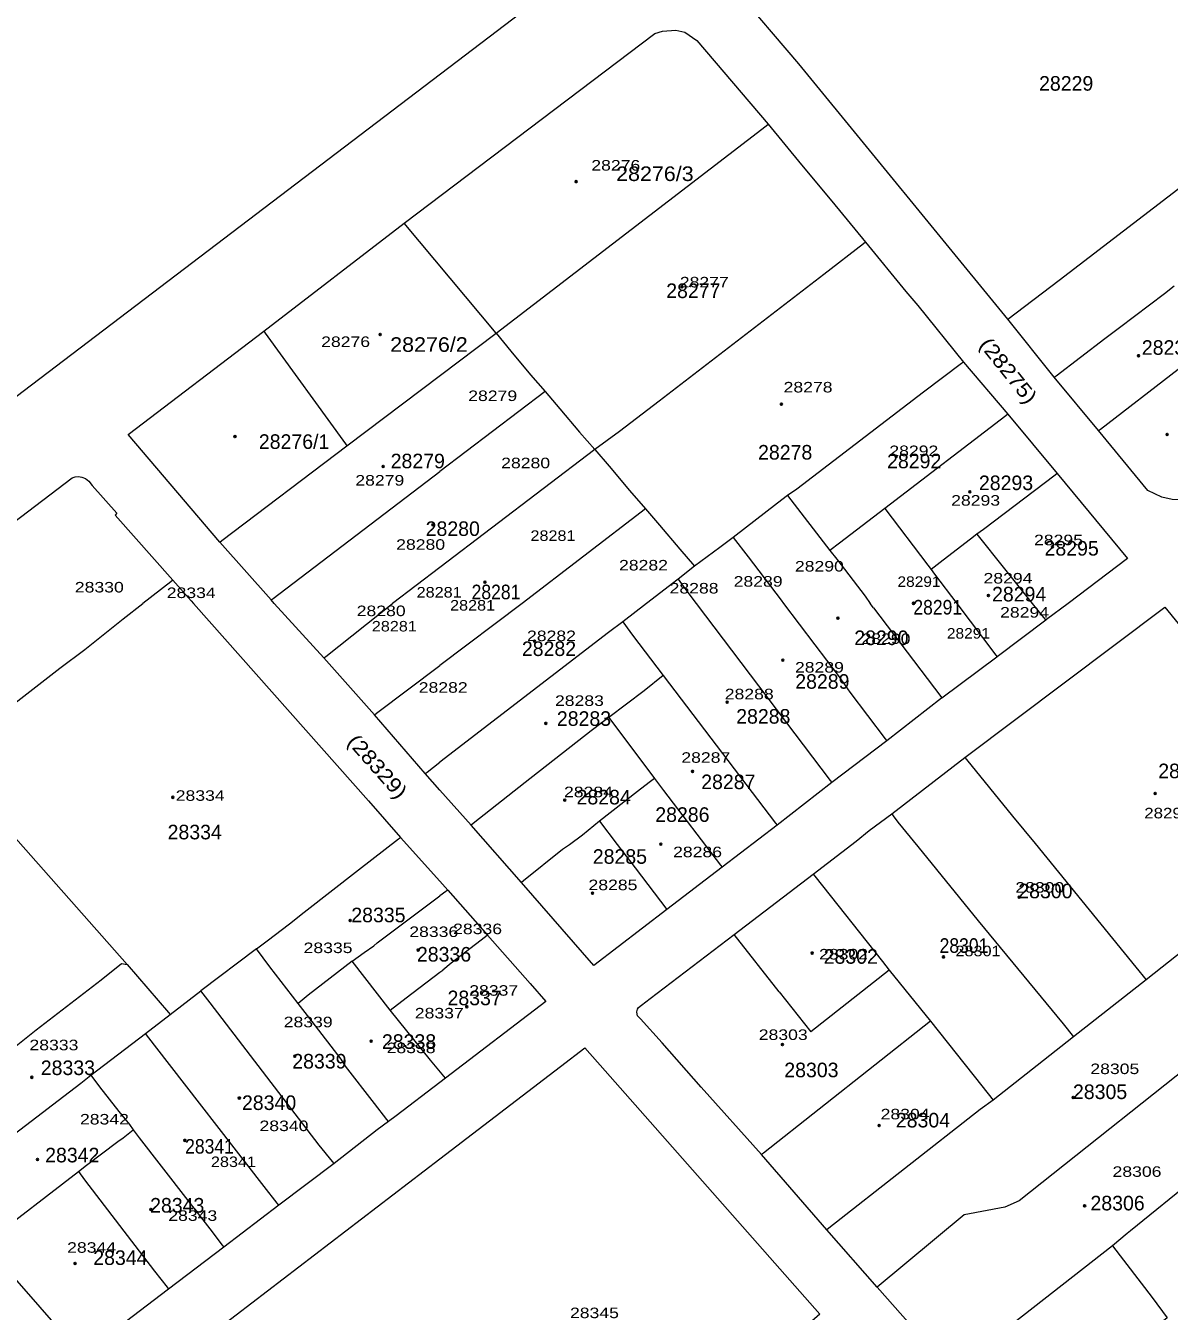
# Model space of a CAD drawing. Extents: x 650553 to 652508, y 239277 to 241647.
# Drawn here: x 651647.7 to 651930.1, y 241075.2 to 241392.6 of the extents above; entities that cross this region are included whole.
import ezdxf

# ---------------------------------------------------------------- set-up
doc = ezdxf.new("R2010")
doc.units = 0
doc.header["$PDMODE"] = 32
doc.header["$PDSIZE"] = 0.5
for name, color, linetype in [('19', 7, 'Continuous'), ('20', 7, 'Continuous'), ('6', 7, 'Continuous')]:
    doc.layers.add(name, color=color, linetype=linetype)
doc.layers.add('3', color=7, linetype='Continuous', lineweight=13)
doc.layers.add('5', color=7, linetype='Continuous', lineweight=13)

msp = doc.modelspace()

# ---------------------------------------------------------------- linework, layer by layer
at = {"layer": '3'}
for points in [[(651370, 241074.13), (651372.52, 241075.56), (651374.02, 241076.72), (651375, 241077.5), (651380.8, 241082.08), (651418.74, 241114.72), (651492.17, 241180.79), (651501.81, 241189.21), (651522.184, 241207.047), (651510.315, 241222.672), (651514.337, 241226.015), (651528.272, 241211.629), (651534.34, 241216.71), (651934.25, 241520.81), (651935.39, 241521.93), (651935.77, 241523.21), (651935.63, 241524.91), (651933.75, 241527.93), (651922.73, 241541.47), (651923.22, 241541.86), (651888.26, 241586.69), (651887.65, 241586.26), (651848.117, 241638.653)], [(651890.22, 241320.18), (651838.628, 241383.147), (651822.772, 241401.85), (651822.162, 241402.878), (651822.324, 241404.195), (651822.971, 241405.485), (651878.911, 241448.551), (651945.895, 241499.372), (651947.853, 241500.347), (651950.067, 241500.78), (651952.377, 241500.815), (651954.829, 241500.052), (651957.24, 241498.606), (651959.178, 241496.936), (651974.53, 241477.34), (652042.61, 241389.52)], [(651741.158, 241343.883), (651803.085, 241390.659), (651804.962, 241391.228), (651808.278, 241391.487), (651810.464, 241390.963), (651813.413, 241388.913), (651831.03, 241368.3)], [(651831.03, 241368.3), (651839.29, 241358.26), (651846.78, 241349.27), (651855.12, 241339.13)], [(651695.68, 241265.13), (651673.011, 241291.694), (651706.487, 241317.205), (651741.158, 241343.883)], [(651855.12, 241339.13), (651865.04, 241326.98), (651868.03, 241323.55), (651879.29, 241309.54), (651890.22, 241296.71), (651902.4, 241282.06)], [(651951.21, 241285.1), (651940.242, 241276.615), (651938.359, 241275.772), (651935.721, 241275.565), (651930.828, 241275.601), (651928.272, 241276.225), (651924.784, 241277.89), (651912.6, 241292.65), (651901.67, 241305.81), (651890.22, 241320.18)], [(651549.43, 241196.89), (651549.98, 241197.62), (651577.87, 241218.95), (651590.72, 241228.7), (651618.7, 241250), (651619.2, 241250.38), (651631.84, 241260.23), (651659.24, 241280.95), (651659.91, 241281.2), (651660.75, 241281.3), (651661.58, 241281.14), (651662.48, 241280.84), (651662.88, 241280.5), (651663.32, 241280.19), (651664.13, 241279.05), (651670.21, 241272.23), (651669.84, 241271.78), (651684.06, 241255.72)], [(651902.4, 241282.06), (651919.77, 241261.09), (651905.13, 241250), (651899.81, 241245.97), (651899.608, 241245.818), (651887.634, 241236.801)], [(651721.3, 241236.51), (651709.1, 241250), (651708.34, 241250.84), (651695.68, 241265.13)], [(651684.06, 241255.72), (651688.58, 241250.63), (651689.14, 241250), (651732.35, 241201.22), (651740.3, 241192.21)], [(651842.16, 241183.11), (651852.77, 241191.31), (651856.01, 241193.9), (651861.55, 241198.02), (651879.6, 241211.94), (651929, 241249.08)], [(651929, 241249.08), (651945.44, 241228.9), (651956.13, 241215.68), (651973.06, 241194.89), (651987.72, 241177.05), (652002.397, 241159.358), (652017.226, 241141.527)], [(651757.7, 241195.26), (651750, 241203.9), (651746.38, 241207.96), (651733.85, 241222.47), (651721.3, 241236.51)], [(651887.634, 241236.801), (651887.54, 241236.73), (651873.931, 241226.591)], [(651873.931, 241226.591), (651873.89, 241226.56), (651860.33, 241216.05)], [(651860.33, 241216.05), (651846.75, 241205.77), (651846.748, 241205.769), (651833.24, 241195.24), (651819.68, 241184.88), (651806, 241174.39)], [(651806, 241174.39), (651788, 241160.63), (651770.13, 241181.08), (651757.7, 241195.26)], [(651740.3, 241192.21), (651750, 241181.42), (651751.98, 241179.23), (651761.75, 241168.1)], [(651829.37, 241113.9), (651814.51, 241130.53), (651804.9, 241141.49), (651799.57, 241147.4), (651799.2, 241147.75), (651798.82, 241148.14), (651798.71, 241148.6), (651798.61, 241149.19), (651798.78, 241149.78), (651799.03, 241150.24), (651799.79, 241150.77), (651801.92, 241152.46), (651801.89, 241152.44), (651822.621, 241168.229), (651842.16, 241183.11)], [(651761.75, 241168.1), (651772.3, 241156.11), (651776.15, 241151.73), (651751.38, 241132.74)], [(651737.63, 240981.45), (651733.68, 240981.72), (651717.72, 241000), (651672.26, 241052.06), (651672.58, 241053.6), (651750, 241112.87), (651779.79, 241135.68), (651785.77, 241140.28)], [(651785.77, 241140.28), (651790.81, 241134.55), (651843.78, 241074.53), (651758.28, 241000), (651750, 240992.68), (651743.815, 240987.217), (651737.63, 240981.45)], [(652017.226, 241141.527), (652026.85, 241129.84), (651999.05, 241104.25), (651938.56, 241048.11), (651910.25, 241021.92), (651891.181, 241043.471), (651876.36, 241060.41), (651857.991, 241081.221), (651845.55, 241095.34), (651829.37, 241113.9)], [(651751.38, 241132.74), (651750, 241131.7), (651739.19, 241123.47), (651737.32, 241122.08)], [(651737.32, 241122.08), (651734.48, 241120.03), (651723.86, 241111.68), (651710.25, 241101.44), (651696.65, 241091.04), (651683.02, 241080.71)], [(651683.02, 241080.71), (651661.58, 241064.36), (651658.09, 241068.4), (651637.53, 241091.91), (651626.47, 241104.9), (651615.22, 241117.65)]]:
    msp.add_lwpolyline(points, dxfattribs=at)
at = {"layer": '5'}
for p, q in [((651902.89, 241329.78), (651954.88, 241369.62)), ((651763.87, 241316.73), (651741.158, 241343.883)), ((651890.22, 241320.18), (651902.89, 241329.78)), ((651775.96, 241302.3), (651750, 241282.54)), ((651800.8, 241273.33), (651770.29, 241250)), ((651882.57, 241267.06), (651896.25, 241250)), ((651750, 241258.88), (651738.31, 241250)), ((651770.29, 241250), (651750, 241234.67)), ((651801.03, 241250), (651795.14, 241245.47)), ((651857.04, 241248.9), (651856.25, 241250)), ((651833.78, 241154.09), (651822.621, 241168.229)), ((651750, 241158.93), (651750.74, 241159.48)), ((651860.94, 241159.47), (651841.57, 241144.24)), ((651833.78, 241154.09), (651841.57, 241144.24)), ((651661.32, 241131.53), (651663.85, 241133.5)), ((651662.21, 241107.67), (651679.53, 241085.1)), ((651916.06, 241091.42), (651925.9, 241078.62))]:
    msp.add_line(p, q, dxfattribs=at)
for points in [[(651763.87, 241316.73), (651830.53, 241367.916), (651831.03, 241368.3)], [(651855.12, 241339.13), (651854.62, 241338.745), (651844.76, 241331.15), (651804.15, 241299.92), (651794.38, 241292.44), (651788.25, 241287.94), (651750, 241258.88)], [(651901.67, 241305.81), (651902.17, 241306.192), (651914.22, 241315.39), (651917.79, 241318.11), (651928.9, 241326.49), (651931.27, 241328.35)], [(651912.6, 241292.65), (651913.1, 241293.036), (651932.26, 241307.83), (651933.94, 241309.27), (651942.09, 241315.47), (651944.08, 241316.85), (651945.26, 241317.85)], [(651695.68, 241265.13), (651696.18, 241265.508), (651727.026, 241288.85), (651763.87, 241316.73)], [(651706.487, 241317.205), (651706.849, 241316.705), (651726.664, 241289.35), (651727.026, 241288.85)], [(651763.87, 241316.73), (651767.54, 241312.22), (651772.39, 241306.41), (651775.96, 241302.3), (651779.58, 241297.99), (651784.48, 241292.24), (651788.25, 241287.94), (651791.78, 241283.83), (651796.81, 241277.87), (651800.8, 241273.33), (651804.19, 241269.3), (651809.26, 241263.38), (651812.88, 241259.17)], [(651879.29, 241309.54), (651878.79, 241309.167), (651869.38, 241302.14), (651838.1, 241278.21), (651835.85, 241276.61), (651833.39, 241274.72), (651822.38, 241266.23), (651819.1, 241263.82), (651812.88, 241259.17), (651808.8, 241255.98), (651801.03, 241250)], [(651890.22, 241296.71), (651889.72, 241296.326), (651859.86, 241273.41), (651848.64, 241264.84), (651846.24, 241263.03)], [(651708.34, 241250.84), (651708.84, 241251.22), (651750, 241282.54)], [(651902.4, 241282.06), (651901.9, 241281.681), (651884.18, 241268.25), (651882.57, 241267.06), (651881.01, 241265.81), (651875.35, 241261.49), (651873.49, 241260.1), (651871.29, 241258.37)], [(651835.85, 241276.61), (651846.24, 241263.03), (651847.99, 241260.89), (651854.99, 241251.76), (651856.25, 241250)], [(651859.86, 241273.41), (651870.47, 241259.44), (651871.29, 241258.37), (651872.16, 241257.18), (651877.61, 241250)], [(651822.38, 241266.23), (651826.09, 241261.5), (651834.24, 241250.76), (651834.82, 241250)], [(651684.06, 241255.72), (651683.56, 241255.332), (651676.69, 241250)], [(651808.8, 241255.98), (651810.06, 241254.27), (651811.25, 241252.7), (651813.29, 241250)], [(651627.9, 241212.17), (651633.91, 241216.69), (651639.01, 241220.73), (651656.16, 241234.02), (651662.35, 241238.63), (651671.78, 241246.2), (651676.69, 241250)], [(651721.3, 241236.51), (651721.8, 241236.907), (651738.31, 241250)], [(651813.29, 241250), (651846.392, 241206.24), (651846.748, 241205.769)], [(651834.82, 241250), (651842.58, 241239.72), (651848.32, 241232.21), (651851.25, 241228.08)], [(651857.04, 241248.9), (651873.651, 241226.96), (651873.931, 241226.591)], [(651877.61, 241250), (651887.3, 241237.24), (651887.634, 241236.801)], [(651896.25, 241250), (651899.028, 241246.54), (651899.608, 241245.818)], [(651795.14, 241245.47), (651791.64, 241242.82), (651750, 241210.75)], [(651795.14, 241245.47), (651796.88, 241243.06), (651797.54, 241242.18), (651805.14, 241232.15)], [(651733.85, 241222.47), (651734.35, 241222.848), (651750, 241234.67)], [(651805.14, 241232.15), (651800.47, 241228.38), (651791.72, 241221.79), (651790.1, 241220.62), (651787.38, 241218.5), (651771.07, 241205.75)], [(651805.14, 241232.15), (651832.859, 241195.74), (651833.24, 241195.24)], [(651851.25, 241228.08), (651859.953, 241216.55), (651860.33, 241216.05)], [(651791.72, 241221.79), (651802.96, 241206.76), (651805.23, 241203.83)], [(651746.38, 241207.96), (651746.88, 241208.345), (651750, 241210.75)], [(651879.6, 241211.94), (651880.007, 241211.44), (651891.35, 241197.49), (651897, 241190.72), (651921.86, 241160.2), (651924.37, 241157.06), (651906.46, 241142.96)], [(651802.96, 241206.76), (651801.69, 241205.8), (651798.82, 241203.57), (651789.38, 241196.26), (651785.23, 241192.75), (651782, 241190.4), (651780.29, 241189.26)], [(651771.07, 241205.75), (651758.2, 241195.652), (651757.7, 241195.26)], [(651805.23, 241203.83), (651819.299, 241185.38), (651819.68, 241184.88)], [(651861.55, 241198.02), (651861.916, 241197.52), (651863.05, 241195.97), (651867.99, 241189.94), (651882.92, 241171.66), (651903.88, 241146.19), (651906.46, 241142.96), (651899.06, 241137.15), (651886.63, 241127.37)], [(651585.63, 241151.78), (651586.13, 241152.148), (651596.73, 241159.96), (651597.72, 241160.75), (651600.47, 241162.97), (651620.63, 241178.18), (651642.7, 241194.85), (651672.75, 241160.85)], [(651789.38, 241196.26), (651793.77, 241190.49), (651798.24, 241184.71), (651806, 241174.39)], [(651973.06, 241194.89), (651972.56, 241194.495), (651969.58, 241192.14), (651955.5, 241181.26), (651947.2, 241174.85), (651933.89, 241164.53), (651924.37, 241157.06)], [(651729.86, 241184.24), (651739.8, 241191.828), (651740.3, 241192.21)], [(651780.29, 241189.26), (651770.63, 241181.483), (651770.13, 241181.08)], [(651704.74, 241164.7), (651707.38, 241166.7), (651712.87, 241170.91), (651716.46, 241173.74), (651729.86, 241184.24)], [(651842.16, 241183.11), (651842.558, 241182.61), (651859.25, 241161.62), (651860.94, 241159.47), (651871.15, 241146.83), (651883.82, 241130.85), (651886.63, 241127.37), (651883.41, 241125.02)], [(651751.98, 241179.23), (651751.48, 241178.859), (651750, 241177.76)], [(651728.31, 241161.69), (651731.33, 241163.78), (651733.67, 241165.47), (651734.48, 241166.21), (651750, 241177.76)], [(651761.75, 241168.1), (651761.25, 241167.711), (651752.8, 241161.13), (651750.74, 241159.48)], [(651737.32, 241122.08), (651736.928, 241122.58), (651733.85, 241126.51), (651726.66, 241135.78), (651725.59, 241137.45), (651718.42, 241146.76), (651714.97, 241151.19), (651708.02, 241160.25), (651704.74, 241164.7), (651690.98, 241154.31)], [(651666.32, 241157.04), (651671.4, 241161.07), (651672.75, 241160.85)], [(651672.75, 241160.85), (651682.978, 241149.01), (651683.422, 241148.496)], [(651751.38, 241132.74), (651747.64, 241137.21), (651737.7, 241149.59), (651728.31, 241161.69), (651717.48, 241153.23), (651714.97, 241151.19)], [(651615.22, 241117.65), (651615.72, 241118.03), (651626.92, 241126.55), (651627.52, 241127.07), (651644.56, 241140.09), (651650.3, 241144.75), (651666.32, 241157.04)], [(651737.7, 241149.59), (651741.66, 241152.62), (651750, 241158.93)], [(651663.85, 241133.5), (651677.33, 241143.81), (651683.422, 241148.496), (651690.98, 241154.31)], [(651723.86, 241111.68), (651723.456, 241112.18), (651720.18, 241116.24), (651693.28, 241151.34), (651690.98, 241154.31)], [(651871.15, 241146.83), (651829.87, 241114.294), (651829.37, 241113.9)], [(651710.25, 241101.44), (651709.85, 241101.94), (651706.57, 241106.04), (651679.57, 241140.95), (651677.33, 241143.81)], [(651943.01, 241142.12), (651893.01, 241102.49), (651889.49, 241100.9), (651879.41, 241099.07), (651857.991, 241081.221)], [(651626.47, 241104.9), (651626.97, 241105.282), (651661.32, 241131.53)], [(651663.85, 241133.5), (651665.97, 241130.65), (651670.71, 241124.54), (651673.38, 241121.31), (651674.3, 241120.02)], [(651883.41, 241125.02), (651846.05, 241095.732), (651845.55, 241095.34)], [(651660.76, 241109.74), (651662.77, 241111.32), (651670.47, 241117.16), (651671.81, 241118.04), (651674.3, 241120.02), (651675.75, 241118.08), (651693.18, 241095.62)], [(651637.53, 241091.91), (651638.03, 241092.294), (651660.76, 241109.74), (651662.21, 241107.67)], [(651936.57, 241108.11), (651920.48, 241095.11), (651919.7, 241094.44), (651916.06, 241091.42)], [(651693.18, 241095.62), (651696.271, 241091.54), (651696.65, 241091.04)], [(651916.06, 241091.42), (651876.86, 241060.801), (651876.36, 241060.41)], [(651679.53, 241085.1), (651682.623, 241081.21), (651683.02, 241080.71)], [(651925.9, 241078.62), (651929.61, 241073.6), (651921.28, 241066.98)]]:
    msp.add_lwpolyline(points, dxfattribs=at)
at = {"layer": '6'}
for p in [(651783.621, 241354.108), (651809.762, 241328.12), (651735.242, 241316.366), (651922.519, 241311.135), (651834.308, 241299.15), (651699.404, 241291.167), (651929.556, 241291.697), (651862.646, 241286.285), (651735.984, 241283.785), (651880.839, 241277.54), (651748.296, 241269.405), (651901.241, 241263.939), (651761.129, 241255.205), (651885.424, 241251.93), (651866.93, 241250), (651848.288, 241246.33), (651773.362, 241240.645), (651834.652, 241235.999), (651820.929, 241225.61), (651776.129, 241220.365), (651812.39, 241208.515), (651684.031, 241202.108), (651780.817, 241201.435), (651926.606, 241203.07), (651804.521, 241190.575), (651787.692, 241178.445), (651893, 241177.45), (651727.865, 241171.7), (651744.607, 241164.41), (651841.915, 241163.675), (651874.346, 241162.695), (651756.613, 241150.42), (651733.03, 241141.885), (651834.554, 241141.065), (651714.189, 241138.19), (651649.225, 241132.985), (651700.473, 241127.875), (651906.357, 241128.035), (651858.438, 241121.085), (651687.011, 241117.425), (651650.64, 241112.705), (651678.657, 241100.365), (651909.198, 241101.265), (651659.907, 241087.05)]:
    msp.add_point(p, dxfattribs=at)

# ---------------------------------------------------------------- texts
at = {"layer": '19'}
for s, p in [('28229', (651897.942, 241376.556)), ('28277', (651805.879, 241325.366)), ('28234', (651923.319, 241311.358)), ('28276/1', (651705.298, 241288.124)), ('28278', (651828.557, 241285.493)), ('28279', (651737.843, 241283.337)), ('28292', (651860.416, 241283.337)), ('28293', (651883.094, 241277.949)), ('28280', (651746.482, 241266.634)), ('28295', (651899.293, 241261.784)), ('28294', (651886.333, 241250.469)), ('28290', (651852.315, 241239.693)), ('28282', (651770.241, 241236.998)), ('28289', (651837.737, 241228.916)), ('28283', (651778.88, 241219.756)), ('28288', (651823.157, 241220.295)), ('28296', (651927.37, 241206.825)), ('28287', (651814.519, 241204.13)), ('28284', (651783.739, 241200.358)), ('28286', (651803.179, 241196.048)), ('28334', (651682.766, 241191.738)), ('28285', (651787.75, 241185.699)), ('28300', (651892.811, 241177.19)), ('28335', (651728.124, 241171.262)), ('28336', (651744.324, 241161.564)), ('28302', (651844.755, 241161.025)), ('28337', (651751.883, 241150.787)), ('28338', (651735.683, 241140.011)), ('28333', (651651.449, 241133.545)), ('28339', (651713.546, 241135.161)), ('28303', (651835.035, 241133.006)), ('28305', (651906.311, 241127.618)), ('28340', (651701.126, 241124.923)), ('28304', (651862.573, 241120.613)), ('28342', (651652.529, 241111.992)), ('28343', (651678.447, 241099.599)), ('28306', (651910.631, 241100.138)), ('28344', (651664.408, 241086.667))]:
    msp.add_text(s, height=3.6, dxfattribs=at).set_placement(p)
for s, width, p in [('28276/3', 1.1, (651793.51, 241354.257)), ('28276/2', 1.1, (651737.728, 241312.09)), ('28281', 0.9, (651757.822, 241251.008)), ('28291', 0.9, (651866.895, 241247.236)), ('28301', 0.9, (651873.373, 241163.719)), ('28341', 0.9, (651687.087, 241114.147))]:
    msp.add_text(s, height=3.6, dxfattribs=dict(at, width=width)).set_placement(p)
at = {"layer": '19', "width": 1.15}
for s, rotation, p in [('(28275)', 308.789, (651882.981, 241313.762)), ('(28329)', 311.535, (651726.909, 241215.682))]:
    msp.add_text(s, height=3.6, rotation=rotation, dxfattribs=at).set_placement(p)
at = {"layer": '20'}
for s, width, p in [('28276', 1.25, (651787.382, 241356.837)), ('28277', 1.25, (651809.232, 241327.998)), ('28276', 1.25, (651720.675, 241313.28)), ('28279', 1.25, (651756.991, 241299.942)), ('28278', 1.25, (651834.86, 241302.064)), ('28280', 1.25, (651765.127, 241283.352)), ('28292', 1.25, (651860.972, 241286.352)), ('28279', 1.25, (651729.111, 241279.069)), ('28293', 1.25, (651876.232, 241274.113)), ('28281', 1.15, (651772.359, 241265.41)), ('28295', 1.25, (651896.693, 241264.341)), ('28280', 1.25, (651739.199, 241263.222)), ('28282', 1.25, (651794.224, 241258.117)), ('28290', 1.25, (651837.66, 241257.854)), ('28294', 1.25, (651884.226, 241254.899)), ('28330', 1.25, (651659.86, 241252.682)), ('28288', 1.25, (651806.709, 241252.434)), ('28289', 1.25, (651822.525, 241254.113)), ('28291', 1.1, (651862.978, 241254.063)), ('28334', 1.25, (651682.551, 241251.307)), ('28281', 1.15, (651744.255, 241251.435)), ('28280', 1.25, (651729.453, 241246.847)), ('28281', 1.15, (651752.501, 241248.215)), ('28294', 1.25, (651888.314, 241246.475)), ('28281', 1.15, (651733.186, 241243.049)), ('28282', 1.25, (651771.505, 241240.678)), ('28290', 1.25, (651854.103, 241239.964)), ('28291', 1.1, (651875.177, 241241.285)), ('28289', 1.25, (651837.667, 241232.908)), ('28282', 1.25, (651744.768, 241227.934)), ('28288', 1.25, (651820.332, 241226.303)), ('28283', 1.25, (651778.407, 241224.671)), ('28287', 1.25, (651809.612, 241210.64)), ('28334', 1.25, (651684.771, 241201.25)), ('28284', 1.25, (651780.64, 241202.137)), ('28296', 1.2, (651923.906, 241196.917)), ('28286', 1.25, (651807.574, 241187.329)), ('28285', 1.25, (651786.687, 241179.193)), ('28300', 1.25, (651892.085, 241178.571)), ('28336', 1.25, (651742.439, 241167.626)), ('28336', 1.25, (651753.262, 241168.333)), ('28335', 1.25, (651716.339, 241163.658)), ('28301', 1.15, (651877.308, 241162.878)), ('28302', 1.25, (651843.618, 241162.089)), ('28337', 1.25, (651757.246, 241153.135)), ('28337', 1.25, (651743.8, 241147.532)), ('28339', 1.25, (651711.43, 241145.344)), ('28303', 1.25, (651828.721, 241142.211)), ('28333', 1.25, (651648.654, 241139.669)), ('28338', 1.25, (651736.842, 241138.957)), ('28305', 1.25, (651910.599, 241133.789)), ('28304', 1.25, (651858.816, 241122.61)), ('28342', 1.25, (651661.125, 241121.345)), ('28340', 1.25, (651705.456, 241119.711)), ('28341', 1.15, (651693.467, 241110.837)), ('28306', 1.25, (651916.084, 241108.418)), ('28343', 1.25, (651682.93, 241097.551)), ('28344', 1.25, (651657.955, 241089.678)), ('28345', 1.25, (651782.118, 241073.534))]:
    msp.add_text(s, height=2.6, dxfattribs=dict(at, width=width)).set_placement(p)

doc.saveas('drawing.dxf')
